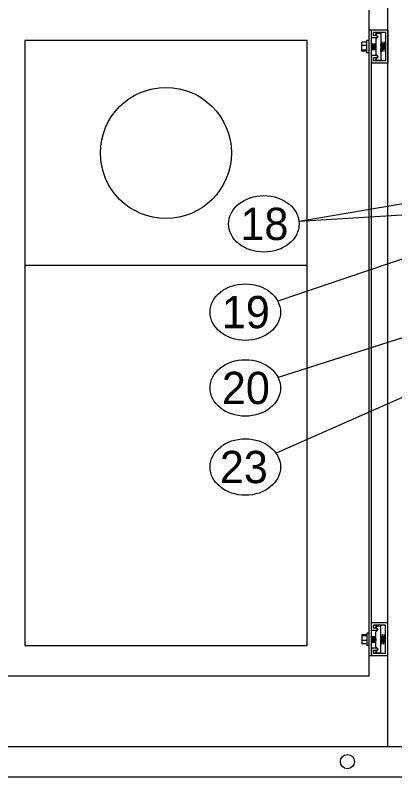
# Model space of a CAD drawing. Extents: x 99862 to 103680, y 99470 to 105076.
# Drawn here: x 102011.9 to 102200.2, y 104497.9 to 104875.4 of the extents above; entities that cross this region are included whole.
import ezdxf

# ---------------------------------------------------------------- set-up
doc = ezdxf.new("R2010")
doc.units = 0
for name, color, linetype in [('Level 1', 7, 'Continuous'), ('Level 15', 7, 'Continuous'), ('Level 20', 7, 'Continuous'), ('Level 40', 7, 'Continuous')]:
    doc.layers.add(name, color=color, linetype=linetype)

msp = doc.modelspace()

# ---------------------------------------------------------------- linework, layer by layer
at = {"layer": 'Level 1'}
for p, q in [((102187.44, 104547.94), (102187.44, 104877.94)), ((102188.54, 104557.94), (102188.54, 104867.94)), ((102156.66, 104751.31), (102016.66, 104751.31)), ((101985.88, 104547.94), (102187.44, 104547.94))]:
    msp.add_line(p, q, dxfattribs=at)
msp.add_lwpolyline([(102016.66, 104562.94), (102156.66, 104562.94), (102156.66, 104862.94), (102016.66, 104862.94)], close=True, dxfattribs=at)
msp.add_circle((102086.66, 104807.12), 32.5, dxfattribs=at)
at = {"layer": 'Level 15'}
for p, q in [((102246.66, 104789.08), (102152.68, 104773.08)), ((102246.66, 104779.08), (102152.68, 104773.08)), ((102246.66, 104769.08), (102142.14, 104733.7)), ((102246.66, 104729.08), (102142.28, 104695.84)), ((102236.66, 104700.56), (102141.33, 104658.26))]:
    msp.add_line(p, q, dxfattribs=at)
msp.add_circle((102176.66, 104505.44), 3.5, dxfattribs=at)
at = {"layer": 'Level 20'}
for centre in [(102135.24, 104771.97), (102126.02, 104728.25), (102126.02, 104690.66), (102126.02, 104651.47)]:
    msp.add_ellipse(centre, major_axis=(-17.5, 0), ratio=0.8, dxfattribs=at)
at = {"layer": 'Level 40'}
for p, q in [((102196.66, 104512.94), (102196.66, 104902.94)), ((102188.54, 104867.94), (102187.44, 104867.94)), ((102196.66, 104867.94), (102188.54, 104867.94)), ((102188.54, 104864.19), (102188.54, 104867.94)), ((102189.63, 104865.28), (102189.63, 104866.84)), ((102195.57, 104866.84), (102189.63, 104866.84)), ((102191.35, 104865.28), (102189.63, 104865.28)), ((102190.72, 104866.43), (102190.72, 104865.96)), ((102190.72, 104866.43), (102193.2, 104866.43)), ((102191.86, 104864.74), (102190.72, 104865.96)), ((102191.35, 104864.19), (102191.35, 104865.28)), ((102193.2, 104866.43), (102193.2, 104853.19)), ((102195.57, 104866.84), (102195.57, 104852.78)), ((102196.66, 104867.94), (102196.66, 104851.69)), ((102186.28, 104862), (102183.78, 104862)), ((102183.78, 104857.63), (102183.78, 104862)), ((102187.44, 104862.8), (102186.28, 104862.8)), ((102186.28, 104856.83), (102186.28, 104862.8)), ((102191.35, 104864.19), (102188.54, 104864.19)), ((102191.86, 104864.74), (102190.72, 104863.51)), ((102190.72, 104863.51), (102190.72, 104856.11)), ((102193.2, 104857.35), (102193.61, 104862.28)), ((102194.03, 104857.35), (102193.61, 104862.28)), ((102194.03, 104857.35), (102194.45, 104862.28)), ((102194.86, 104857.35), (102194.45, 104862.28)), ((102194.86, 104857.35), (102195.28, 104862.28)), ((102195.57, 104858.89), (102195.28, 104862.28)), ((102186.28, 104860.32), (102183.78, 104860.32)), ((102186.28, 104858.13), (102183.78, 104858.13)), ((102186.28, 104857.63), (102183.78, 104857.63)), ((102188.54, 104861.17), (102190.72, 104861.17)), ((102188.54, 104858.46), (102188.79, 104861.17)), ((102188.54, 104858.46), (102190.72, 104858.46)), ((102188.79, 104858.46), (102189.03, 104861.17)), ((102189.03, 104858.46), (102189.28, 104861.17)), ((102189.28, 104858.46), (102189.53, 104861.17)), ((102189.53, 104858.46), (102189.78, 104861.17)), ((102189.78, 104858.46), (102190.03, 104861.17)), ((102190.03, 104858.46), (102190.28, 104861.17)), ((102190.28, 104858.46), (102190.53, 104861.17)), ((102190.53, 104858.46), (102190.72, 104860.54)), ((102193.2, 104860.42), (102193.27, 104861.17)), ((102193.2, 104861.17), (102193.88, 104861.17)), ((102193.2, 104858.46), (102193.88, 104858.46)), ((102193.27, 104858.46), (102193.51, 104861.17)), ((102193.27, 104858.46), (102193.51, 104861.17)), ((102193.51, 104858.46), (102193.76, 104861.17)), ((102193.51, 104858.46), (102193.76, 104861.17)), ((102193.76, 104858.46), (102193.88, 104859.7)), ((102193.88, 104861.17), (102193.88, 104858.46)), ((102187.44, 104856.83), (102186.28, 104856.83)), ((102188.54, 104855.44), (102188.54, 104851.69)), ((102191.35, 104855.44), (102188.54, 104855.44)), ((102189.63, 104854.34), (102189.63, 104852.78)), ((102191.35, 104854.34), (102189.63, 104854.34)), ((102191.86, 104854.89), (102190.72, 104856.11)), ((102191.86, 104854.89), (102190.72, 104853.67)), ((102191.35, 104855.44), (102191.35, 104854.34)), ((102196.66, 104851.69), (102188.54, 104851.69)), ((102195.57, 104852.78), (102189.63, 104852.78)), ((102190.72, 104853.19), (102190.72, 104853.67)), ((102190.72, 104853.19), (102193.2, 104853.19)), ((102196.66, 104574.19), (102188.54, 104574.19)), ((102188.54, 104570.44), (102188.54, 104574.19)), ((102189.63, 104571.53), (102189.63, 104573.09)), ((102195.57, 104573.09), (102189.63, 104573.09)), ((102191.35, 104571.53), (102189.63, 104571.53)), ((102190.72, 104572.68), (102193.2, 104572.68)), ((102190.72, 104572.68), (102190.72, 104572.21)), ((102191.86, 104570.99), (102190.72, 104572.21)), ((102191.86, 104570.99), (102190.72, 104569.76)), ((102191.35, 104570.44), (102191.35, 104571.53)), ((102193.2, 104559.44), (102193.2, 104572.68)), ((102195.57, 104559.03), (102195.57, 104573.09)), ((102196.66, 104557.94), (102196.66, 104574.19)), ((102186.28, 104568.25), (102183.78, 104568.25)), ((102183.78, 104568.25), (102183.78, 104563.88)), ((102186.28, 104567.74), (102183.78, 104567.74)), ((102187.44, 104569.05), (102186.28, 104569.05)), ((102186.28, 104569.05), (102186.28, 104563.08)), ((102191.35, 104570.44), (102188.54, 104570.44)), ((102188.54, 104567.42), (102190.72, 104567.42)), ((102188.54, 104567.42), (102188.79, 104564.71)), ((102188.79, 104567.42), (102189.03, 104564.71)), ((102189.03, 104567.42), (102189.28, 104564.71)), ((102189.28, 104567.42), (102189.53, 104564.71)), ((102189.53, 104567.42), (102189.78, 104564.71)), ((102189.78, 104567.42), (102190.03, 104564.71)), ((102190.03, 104567.42), (102190.28, 104564.71)), ((102190.28, 104567.42), (102190.53, 104564.71)), ((102190.53, 104567.42), (102190.72, 104565.34)), ((102190.72, 104562.36), (102190.72, 104569.76)), ((102193.2, 104568.53), (102193.61, 104563.6)), ((102193.2, 104567.42), (102193.88, 104567.42)), ((102193.27, 104567.42), (102193.51, 104564.71)), ((102193.27, 104567.42), (102193.51, 104564.71)), ((102193.51, 104567.42), (102193.76, 104564.71)), ((102193.51, 104567.42), (102193.76, 104564.71)), ((102194.03, 104568.53), (102193.61, 104563.6)), ((102193.76, 104567.42), (102193.88, 104566.18)), ((102193.88, 104564.71), (102193.88, 104567.42)), ((102194.03, 104568.53), (102194.45, 104563.6)), ((102194.86, 104568.53), (102194.45, 104563.6)), ((102194.86, 104568.53), (102195.28, 104563.6)), ((102195.57, 104566.99), (102195.28, 104563.6)), ((102186.28, 104565.56), (102183.78, 104565.56)), ((102186.28, 104563.88), (102183.78, 104563.88)), ((102188.54, 104564.71), (102190.72, 104564.71)), ((102193.2, 104565.45), (102193.27, 104564.71)), ((102193.2, 104564.71), (102193.88, 104564.71)), ((102187.44, 104563.08), (102186.28, 104563.08)), ((102188.54, 104561.69), (102188.54, 104557.94)), ((102191.35, 104561.69), (102188.54, 104561.69)), ((102189.63, 104560.59), (102189.63, 104559.03)), ((102191.35, 104560.59), (102189.63, 104560.59)), ((102191.86, 104561.14), (102190.72, 104562.36)), ((102191.86, 104561.14), (102190.72, 104559.92)), ((102190.72, 104559.44), (102190.72, 104559.92)), ((102190.72, 104559.44), (102193.2, 104559.44)), ((102191.35, 104561.69), (102191.35, 104560.59)), ((102188.54, 104557.94), (102187.44, 104557.94)), ((102196.66, 104557.94), (102188.54, 104557.94)), ((102195.57, 104559.03), (102189.63, 104559.03)), ((101976.66, 104512.94), (102376.66, 104512.94)), ((101976.66, 104497.94), (102376.66, 104497.94))]:
    msp.add_line(p, q, dxfattribs=at)

# ---------------------------------------------------------------- texts
at = {"layer": 'Level 20'}
for s, p in [('18', (102123.61, 104763.97)), ('19', (102114.4, 104720.25)), ('20', (102114.4, 104682.66)), ('23', (102113.4, 104643.47))]:
    msp.add_text(s, height=16, dxfattribs=at).set_placement(p)

doc.saveas('drawing.dxf')
